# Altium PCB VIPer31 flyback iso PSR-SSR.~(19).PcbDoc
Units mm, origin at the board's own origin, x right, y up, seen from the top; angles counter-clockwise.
Board outline 152.4 x 101.6 mm, 2 copper layers (Top Layer, Bottom Layer); 61 components, 31 nets, 135 pads, 7 vias.
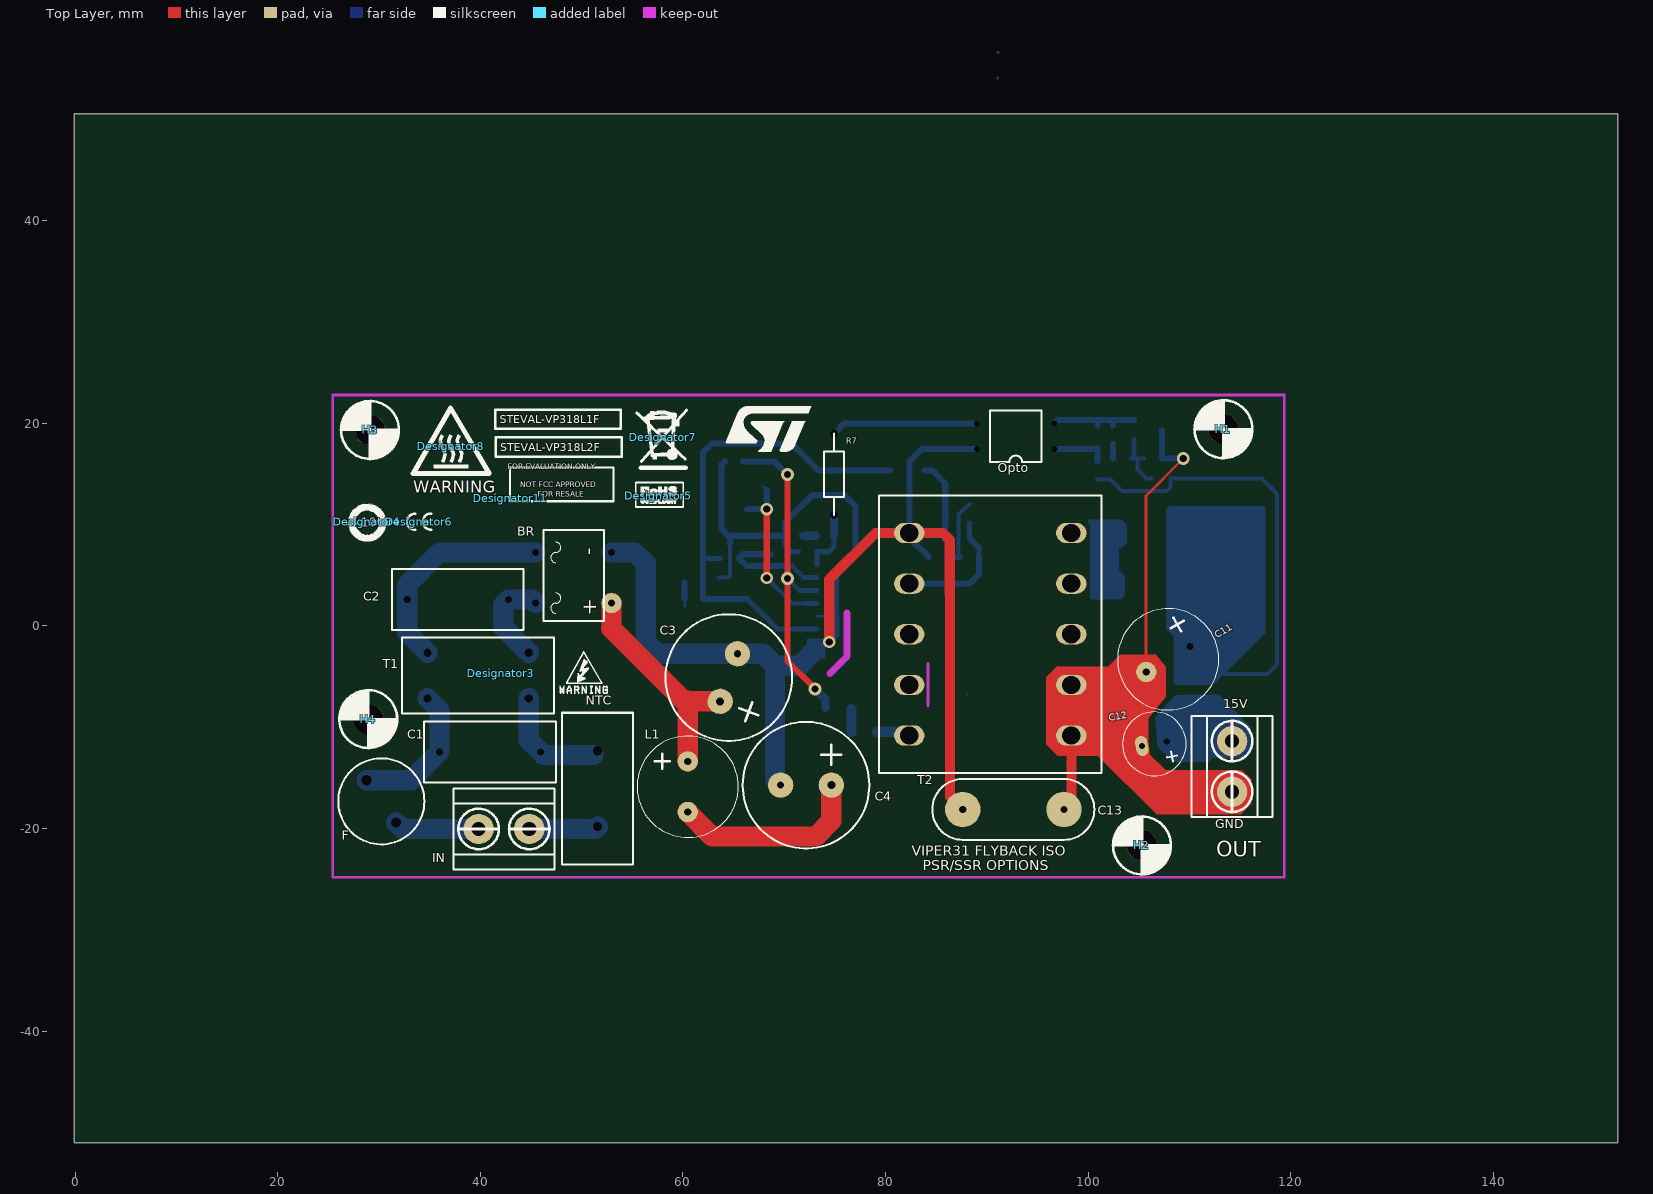
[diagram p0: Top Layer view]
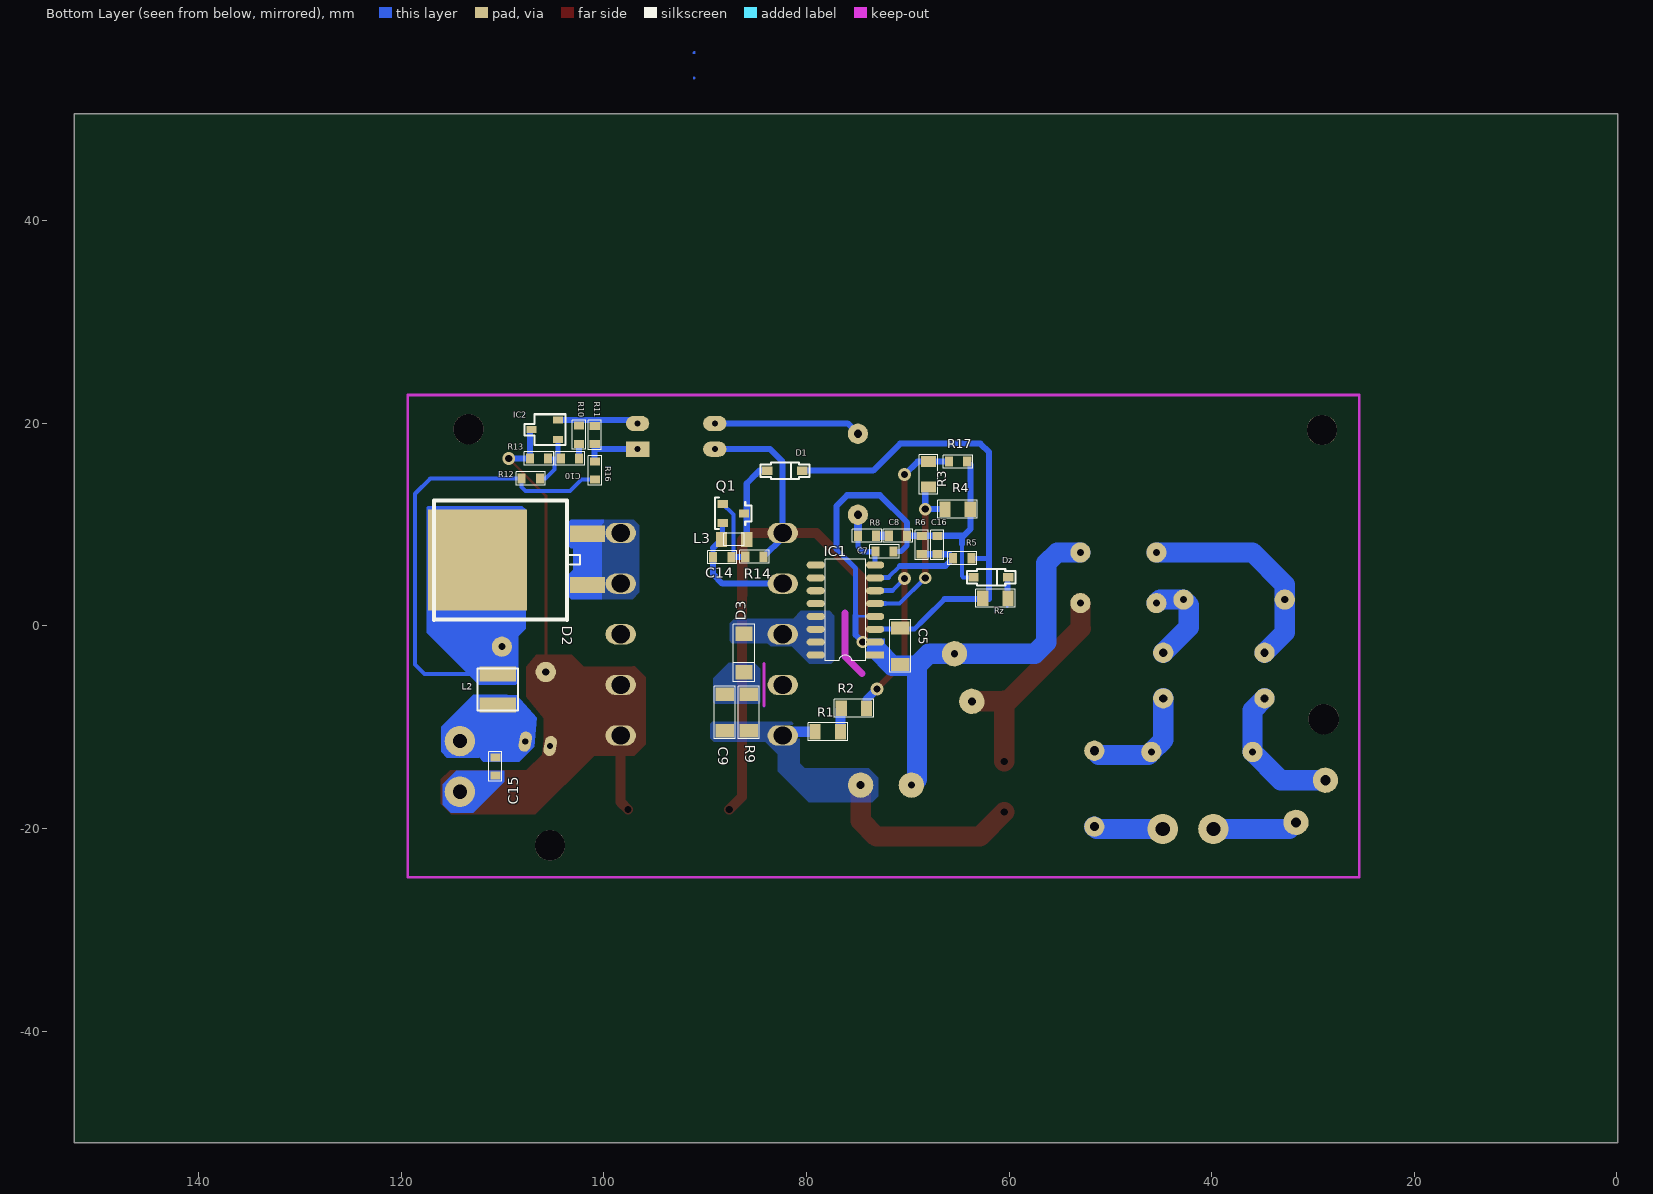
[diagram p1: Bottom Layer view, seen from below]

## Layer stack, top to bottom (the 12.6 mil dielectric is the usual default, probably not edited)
Top Solder: solder mask 0.0102, Solder Resist, Dk 3.5
Top Layer: signal copper 0.0356
Dielectric 1: dielectric 0.32, FR-4, Dk 4.8
Bottom Layer: signal copper 0.0356
Bottom Solder: solder mask 0.0102, Solder Resist, Dk 3.5

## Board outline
-0.1,-51.05 152.3,-51.05 152.3,50.55 -0.1,50.55

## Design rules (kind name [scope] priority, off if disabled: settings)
Clearance Clearance_1 [All] p1: gap=0.2 ignorepadtopadclearanceinfootprint=FALSE except(0: Arc-Hole Track-Hole SMDPad-Hole THPad-Hole Via-Hole Fill-Hole Poly-Hole Region-Hole Text-Hole)
Clearance [All] p2: gap=0.254 ignorepadtopadclearanceinfootprint=FALSE except(0: Arc-Poly Arc-Hole Track-Poly Track-Region Track-Hole SMDPad-Poly SMDPad-Hole THPad-Poly THPad-Hole Via-Poly Via-Hole Fill-Poly Fill-Hole Poly-Poly Poly-Hole Region-Hole Text-Hole)
PolygonConnect [All] p1: connectstyle=Direct reliefconductorwidth=0.254 reliefentries=4 polygonreliefangle="90 Angle" airgapwidth=0.254
RoutingVias [All] p1: holewidth=0.711 width=1.27 viastyle="Through Hole" minholewidth=0.711 minwidth=1.27 maxholewidth=0.711 maxwidth=1.27
SolderMaskExpansion [All] p1: expansion=0.102
Width [All] p1: maxlimit=2 minlimit=0.254 preferedwidth=0.254 minimp=50.000000 maximp=50.000000 favimp=50.000000
30 further rules are at their usual default settings.

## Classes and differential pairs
component class "VIPer31 flyback iso PSR-SSR": BR C1 C2 C4 C5 C7 C8 C9 C10 C13 C14 C16 D1 D2 D3 Dz F H1 H2 H3 H4 IC1 IC2 IN L1 L3 NTC Opto Q1 R1 R2 R3 R4 R5 R6 R7 R8 R9 R10 R11 R12 R13 R14 R16 R17 Rz T1 T2 VR1

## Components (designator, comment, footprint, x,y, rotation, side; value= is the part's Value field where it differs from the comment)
BR "MB6S-E3" BRIDGE 45.45,7.25 r270 top
C1 "100nF" CAP-13X6 45.95,-12.45 r180 top value="100 pF +/-5%, 250 Vdc"
C2 "100nF" CAP-13X6 42.775,2.6 r180 top value="100 pF +/-5%, 250 Vdc"
C3 "22 uF 400 Vcc" CAPOL-5X12.5 63.675,-7.45 r70 top value="68 uF +/-20%, 400 Vcc, +105°C"
C4 "22 uF 400 Vcc" CAPOL-5X12.5 74.65,-15.725 r180 top value="68 uF +/-20%, 400 Vcc, +105°C"
C5 "4.7uF" R-1206-B2 70.75,-0.2 r270 top value="10uF +/-20%, 35 Vcc, +105°C"
C7 "1 nF 200 Vdc" R-0603-B2 73.2,7.35 r180 top value="1 nF +/-5%, 200 Vdc"
C8 "NC" R-0603-B2 71.875,8.9 r180 top
C9 "1nF +/-5% 630V" R-1206-B2 88.075,-10.35 r90 top value="1 nF 630 Vdc"
C10 "47nF" R-0603-B2 104.265,16.525 r180 top value="22nF, ±10%, 100Vcc"
C11 "680 uF, 25 Vcc" CAPOL-5X10#1 110.075,-2.05 r210 top value="470 uF +/-20%, 35 Vcc, +105°C"
C12 "100 uF, 35 Vcc" CAPOL-2.5X6.3 107.775,-11.425 r10 top value="100 uF +/-20%, 35 Vcc, +105°C"
C13 "2.2nF 250Vac X1 Y2" MYLAR-10X6 97.625,-18.125 r180 top value="2.2 nF 250 Vac X1 Y2"
C14 "NC" R-0603-B2 87.425,6.775 r0 top
C15 "100 nF" R-0603-B2 110.725,-12.975 r270 top value="100nF ±10%, 25 Vcc"
C16 "NC" R-0603-B2 67.075,7.075 r90 top
D1 "1N4148" SOD-123 83.875,15.325 r0 top value="1 A, 150 V"
D2 "STPS20200CG-TR" D2PAK 101.625,4.025 r90 bottom
D3 "MRA4007T3G" SMA-2 86.175,-0.775 r90 top
Designator3 "Comment" High-Voltage-Logo-5mm 42,-4.675 r0 top
Designator4 "Comment" "RoHS-CH-Logo 10-4mm" 28.775,10.275 r0 top
Designator5 "Comment" RoHS-EU-Logo-4.5mm 57.55,12.85 r0 top
Designator6 "Comment" "CE 1.85 x 2.76mm" 33.9,10.275 r0 top
Designator7 "Comment" WASTE_5mm 58,18.65 r0 top
Designator8 "Comment" "HOT SURFACE-logo-8mm" 37.05,17.725 r0 top
Designator11 "Comment" ADVISE_small 42.95,12.6 r0 top
Dz "22" SOD-123 63.525,4.8 r0 top value="18W, 500 mW"
F "2A" Fuse_3821200041_Wick 31.675,-19.4 r125 top
H1 "HOLE" FORO 113.375,19.425 r0 top
H2 "HOLE" FORO 105.325,-21.675 r0 top
H3 "HOLE" FORO 29.1,19.35 r0 top
H4 "HOLE" FORO 28.925,-9.2 r0 top
IC1 "VIPER31_SO16" SO-16N_2 73.225,-2.875 r90 top
IC2 "TS3431BILT" SOT23-3-MIRR 104.54,20.325 r270 top value="1.24 V VREF SHUNT"
IN "input connector" SM.2VITE 39.825,-20.05 r0 top
L1 "1mH" CAPOL-5X10#2 60.475,-13.375 r270 top value="3.3UH 3.23A 33 MOHM"
L2 "3.3 uH" WE_74404043033A_4x4 110.5,-4.75 r90 top value="3.3UH 3.23A 33 MOHM"
L3 "10uH" R-0805-B 85.9,8.525 r0 top value="3.3UH 3.23A 33 MOHM"
NTC "10 Ohm" B57237S100M-NTC 51.575,-19.825 r90 top
Opto "SFH610A-2" DIP4 96.675,17.45 r180 top
OUT "output connector" SM.2VITE 114.225,-11.375 r270 top
Q1 "BC807" BC817_NEW 88.275,10.3 r90 top value="PNP Transitstor 0.5A, 45 V, hfe 30"
R1 "3 MOhm" R-0805-B2 76.65,-10.45 r0 top value="1MOhm +/-5%"
R2 "3 MOhm" R-0805-B2 74.075,-8.125 r0 top value="1MOhm +/-5%"
R3 "6.8 kOhm" R-0805-B2 67.95,13.725 r90 top value="1MOhm +/-5%"
R4 "60.4 kOhm" R-0805-B2 63.825,11.525 r0 top value="1MOhm +/-5%"
R5 "NC" R-0603-B2 65.525,6.675 r180 top
R6 "0R" R-0603-B2 68.625,8.875 r270 top value="0 Ohm, 0.25W"
R7 "0R" RES-1/4W-3 74.925,18.975 r270 top value="0 Ohm, 0.25W"
R8 "NC" R-0603-B2 73.125,8.9 r0 top
R9 "220 kOhm" R-1206-B2 85.7,-6.75 r270 top value="220 KOhm +/-5%, 0.33W, 1206"
R10 "82k" R-0603-B2 102.465,17.975 r90 top value="470kO ±1%, 0.1W"
R11 "15k" R-0603-B2 100.915,19.75 r270 top value="22KO ±1%, 0.1W"
R12 "100 kOhm" R-0603-B2 106.325,14.55 r0 top value="130 kO ±1%, 0.1 W"
R13 "9 kOhm" R-0603-B2 107.315,16.525 r180 top value="15 kO ±1%, 0.1W, 0603"
R14 "NC" R-0603-B2 84.25,6.825 r0 top
R16 "2.2k" R-0603-B2 100.89,16.25 r270 top value="470O ±1%, 0.1W"
R17 "RESISTENZA" R-0603-B2 64.125,16.225 r0 top
Rz "12R" R-0805-B2 60.1,2.725 r0 top value="47O ±1%, 0.125W"
T1 "2 X 10 mH" WE_744821110_Choke 44.775,-2.65 r90 top
T2 "TRANSFORMER_WURTH_750317580-VIPer31" WURTH-750317580-VIPer31 82.35,9.175 r0 top

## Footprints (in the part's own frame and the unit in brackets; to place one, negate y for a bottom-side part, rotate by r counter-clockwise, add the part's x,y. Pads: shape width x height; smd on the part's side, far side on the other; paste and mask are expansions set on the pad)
ADVISE_small [mm]
  silkscreen extent -0.04,-0.29 10.2,3.02
B57237S100M-NTC [mm]
  round 0 / inner round 0 / far side round 2 hole 0.9: 1(0,0) 2(7.5,0)
  silkscreen extent -3.75,-3.5 11.25,3.5
BC817_NEW [mm]
  rect 0.8x1 smd far side: 1(1.75,0) 2(-0.15,0) 3(0.8,2.1)
BRIDGE [mm]
  round 0 / inner round 0 / far side round 2 hole 0.7: 1(0,0) 3(5,0) 4(0,7.5)
  round 2 hole 0.7: 2(5,7.5)
  silkscreen extent -2.22,0.78 6.77,6.78
CAP-13X6 [mm]
  round 0 / inner round 0 / far side round 2 hole 0.7: 1(0,0) 2(10,0)
  silkscreen extent -1.5,-3 11.5,3
CAPOL-2.5X6.3 [mm]
  round 0 / inner round 0 / far side oval 1.2x2 hole 0.6: 1(0,0)
  oval 1.2x2 hole 0.6: 2(-2.5,0)
  silkscreen extent -4.4,-3.15 1.9,3.15
CAPOL-5X10#1 [mm]
  round 0 / inner round 0 / far side round 2 hole 0.7 unplated: 1(0,0)
  round 2 hole 0.7: 2(5,0)
  silkscreen extent -2.5,-5 7.5,5
CAPOL-5X10#2 [mm]
  round 2 / inner round 0 / far side round 0 hole 0.7: 1(0,0) 2(5,0)
  silkscreen extent -2.5,-5 7.5,5
CAPOL-5X12.5 [mm]
  round 2.5 hole 0.8: 1(0,0)
  round 2.5 hole 0.7: 2(5,0)
  silkscreen extent -3.75,-6.25 8.75,6.25
"CE 1.85 x 2.76mm" [mm]
  silkscreen extent -1.15,-0.8 1.25,0.82
D2PAK [mm]
  rect 1.6x3.5 smd: 1(0,0) 2(5.08,0)
  rect 10x9.75 smd: 3(2.475,10.85)
  silkscreen extent -3.42,0.72 8.35,15.15
DIP4 [mm]
  rect 0x0 / inner rect 0x0 / far side rect 2.3x1.5 hole 0.6 unplated: 1(0,0)
  round 0 / inner round 0 / far side oval 2.3x1.5 hole 0.6 unplated: 2(0,-2.54) 3(7.62,-2.54) 4(7.62,0)
  silkscreen extent 1.27,-3.81 6.35,1.27
FORO [mm]
  round 3 hole 3: 1(0,0)
  silkscreen extent -2.88,-2.88 2.86,2.86
Fuse_3821200041_Wick [mm]
  round 0 / inner round 0 / far side round 2.5 hole 1: 1(0,0) 2(5.08,0)
  silkscreen extent -1.71,-4.25 6.79,4.25
High-Voltage-Logo-5mm [mm]
  silkscreen extent 5.83,-1.99 10.55,2.13
"HOT SURFACE-logo-8mm" [mm]
  silkscreen extent -3.68,-2.67 3.81,3.81
MYLAR-10X6 [mm]
  round 3.5 / inner round 0 / far side round 0 hole 0.7: 1(0,0) 2(10,0)
  silkscreen extent -3,-3 13,3
R-0603-B2 [mm]
  rect 0.8x1 smd far side: 1(0,0) 2(1.8,0)
R-0805-B [mm]
  rect 1.1x1.5 smd far side: 1(0,0) 2(2.5,0)
R-0805-B2 [mm]
  rect 1.1x1.5 smd far side: 1(0,0) 2(2.5,0)
R-1206-B2 [mm]
  rect 1.3x1.8 smd far side: 1(0,0) 2(3.6,0)
RES-1/4W-3 [mm]
  round 0 / inner round 0 / far side round 2 hole 0.8: 1(0,0) 2(8,0)
  silkscreen extent 0,-1 8,1
"RoHS-CH-Logo 10-4mm" [mm]
  silkscreen extent -2.05,-1.88 2.14,1.74
RoHS-EU-Logo-4.5mm [mm]
  silkscreen extent -2.21,-1.11 2.5,1.31
SM.2VITE [mm]
  round 3 hole 1.4: 1(0,0) 2(5,0)
  silkscreen extent -2.5,-4 7.5,4
SMA-2 [mm]
  rect 1.45x1.65 smd far side: 1(0,0) 2(-3.8,0)
SO-16N_2 [mm]
  rect 0.7x1.8 smd far side: 1(0,0)
  oval 0.7x1.8 smd far side: 2(1.27,0) 3(2.54,0) 4(3.81,0) 5(5.08,0) 6(6.35,0) 7(7.62,0) 8(8.89,0) 9(8.89,-5.864) 10(7.62,-5.864) 11(6.35,-5.864) 12(5.08,-5.864) 13(3.81,-5.864) 14(2.54,-5.864) 15(1.27,-5.864) 16(0,-5.864)
SOD-123 [mm]
  rect 1x0.8 smd far side: 1(0,0) 2(-3.45,0)
SOT23-3-MIRR [mm]
  rect 0.7x1 smd far side: 1(1.9,0) 2(0.95,2.6) 3(0,0)
WASTE_5mm [mm]
  silkscreen extent -2.67,-3.03 2.46,2.77
WE_744821110_Choke [mm]
  round 0 / inner round 0 / far side round 2 hole 0.8: 1(-4.5,0) 2(0,0) 3(0,10) 4(-4.5,10)
  silkscreen extent -6,-2.5 1.5,12.5
WE_74404043033A_4x4 [mm]
  rect 1.5x3.6 smd far side: 1(0,0) 2(-3.05,0)
WURTH-750317580-VIPer31 [mm]
  oval 3x2 hole 1.8: 1(0,0) 2(0,-5) 3(0,-10) 4(0,-15) 5(0,-20) 6(16,-20) 7(16,-15) 8(16,-10) 9(16,-5) 10(16,0)
  silkscreen extent -3,-23.7 19,3.7

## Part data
BR: library part BRIDGE1, "Diode Bridge"
C1 C2: library part CAP, "100 pF 250 Vdc multi layer capacitor", Package="SMD 0603", Part number=CGA3E3C0G2E101J080AA
C3 C4: library part "Cap Pol1", "Polarized Capacitor (Radial)", Package="TH D{}18 mm, H{}25 mm, P{}7.5 mm", Part number=400BXC68MEFC18X25
C5: library part "Cap Pol1", "Vcc cap 4.7uF 50 Vcc, Kemet", Package="TH D{}4 mm, H{}7 mm, P{}1.5 mm", Part number=35ML10MEFC4X7
C7: library part CAP, "1 nF 200 Vdc multi layer capacitor", Package="SMD 0603", Part number=C0603C102J2GACAUTO
C8 C14 C16: library part CAP, Package="SMD 0603"
C9: library part CAP, "1 nF 630 V multi layer capacitor", Package="SMD 1206", Part number=C3216C0G2J102J085AA
C10: library part CAP, "22 nF +/-10%, 100 Vcc, MLCC", Package="SMD 0603", Part number=GCM188R72A223KA37D
C11: library part "Cap Pol1", "470 uF +/-20%, 35 Vcc, +105°C", Package="TH D{}10 mm, H{}12.5 mm, P{}5 mm", Part number=25ZLH470MEFC10X12.5
C12: library part "Cap Pol1", "100 uF +/-20%, 35 Vcc, +105°C", Package="TH D{}6.3 mm, H{}11 mm, P{}2.5 mm", Part number=35ZLH100MEFC6.3X11
C13: library part CAP, "2.2 nF 2000 V single layer capacitor", Package="TH 8 mm X 5 mm, P 7.5 mm", Part number=DE2E3KY222MA2BM01F
C15: library part CAP, "100nF ±10%, 25 Vcc, MLCC", Package="SMD 0603", Part number=C0603C104K3RACTU
D1: library part Diode, "small signal diode", Part number=STPS1150A
D2: library part DIODO-DUAL-2
D3: library part Diode, "Silicon Diode, 1 A, 1000 V"
Dz: library part "D Zener", "Zener Diode", Package="SOD 123", Part number=MMSZ5248B-V-GS08
F: library part "Fuse 1", "Fuse 2A,  250 Vca", Package="SMD 10.1mm X 1.43 mm", Part number=3403.0169.24
IC1: "Integrato"
IC2: library part TS432, "1.24 V VREF SHUNT", Package=SOT23-3, Part number=TS432ILT
IN OUT: library part M.2VITE, "Morsetti"
L1 L2 L3: library part Inductor, "FIXED IND 3.3UH 3.23A 33 MOHM", Package="Lu x La: 0,157 x 0,157\" (4,00 x 4,00 mm)", Part number=74404043033A
NTC: library part Res2, Package="TH 9 mm X 4 mm , P 5mm", Part number=NTPA7100LBMB0
Opto: library part OPTO_1, "Opto ingresso 60 Vdc", Package="TH, DIP4"
Q1: library part PNP_BC807, "PNP Transitstor 0.5A, 45 V, hfe 30", Package=SOT23-3L, Part number=BC807-40LT3G
R1 R2: library part Res1, "3 MOhm +/-1%  0.125W, 0805 Vishay", Package="SMD 1206", Part number=ERJP08J105V
R3: library part Res1, "6.8 kOhm +/-1% 0.125W, 0805 Panasonic", Package="SMD 1206", Part number=ERJP08J105V
R4: library part Res1, "60.4 kOhm +/-1% 0.125W, 0805 Panasonic", Package="SMD 1206", Part number=ERJP08J105V
R5 R8 R14: library part Res1, "Not connected", Package="SMD 0603"
R6 R7: library part Res1, "0O, 0.25W, pkg 0603, serie CRCW", Package="SMD 0603", Part number=CRCW06030000Z0EAHP
R9: library part Res1, "220 KOhm +/-5%, 0.33W, 1206, serie ERJT08", Package="SMD 1206", Part number=ERJT08J224V
R10: library part Res1, "470kO ±1%, 0.1W", Package="SMD 0603", Part number=CRCW0603470KFKEA
R11: library part Res1, "22KO ±1%, 0.1W", Package="SMD 0603", Part number=CRCW060322K0FKEA
R12: library part Res1, "Not connected", Package="SMD 0603", Part number=CRCW0603130KFKEA
R13: library part Res1, "15 kO ±1%, 0.1W, 0603", Package="SMD 0603", Part number=CRG0603F15K
R16: library part Res1, "470O ±1%, 0.1W", Package="SMD 0603", Part number=CRCW0603470RFKEA
R17: "Resistor"
Rz: library part Res1, "47O ±1%, 0.125W", Package="SMD 0805", Part number=CRG0805F47R
T1: library part "CM CHOKE", "Common Mode Choke, Lo=10 mH, Rdc=350 mOhm, Idc=0.7A, Un=230 Vac", Package="TH D 15 mm X 7.5 mm", Part number=744821110
T2: "Center-tapped transformer"

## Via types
v1: diameter 1.27, hole 0.711, Top Layer to Bottom Layer, 4 vias
v2: diameter 1.2, hole 0.7, Top Layer to Bottom Layer, 3 vias

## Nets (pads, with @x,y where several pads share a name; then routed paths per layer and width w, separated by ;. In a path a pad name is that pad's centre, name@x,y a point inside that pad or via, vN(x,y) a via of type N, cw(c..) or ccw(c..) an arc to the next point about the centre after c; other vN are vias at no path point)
15V: C12.1 C15.1 L2.2 OUT.1
GND: BR.4 C3.2 C4.2 C5.2 C7.2 C8.2 C13.2 C16.2 Dz.1 IC1.1 IC1.2 IC1.4 Opto.4 R4.1 R6.1 R14.1 R17.1 T2.1 | length 155.7
  Top Layer w0.254: 86.375,-16.875 86.375,-16.625
  Top Layer w1: v2(74.445,-1.605) 74.445,4.595 79.025,9.175 T2.1 85.675,9.175 86.35,8.5 86.35,3.05 ; 86.375,-16.875 C13.2 ; 86.375,-16.625 86.375,3.325
  Bottom Layer w0.254: 64.475,8.9 64.65,8.725 ; IC1.4 75.06,0.935 75.15,1.025 ; T2.1@82.35,8.725 T2.1
  Bottom Layer w0.4: Dz.1 64.525,4.8 64.65,4.925 64.65,8.1
  Bottom Layer w0.5: C8.2 70.075,7.95 70.675,7.35 C7.2 ; 75.15,1.025 75.15,5.675 77.05,7.575
  Bottom Layer w0.6: R17.1 63.825,15.925 R4.1 63.825,9.55 64.475,8.9 68.625,8.9 C8.2 70.075,10.225 72.75,12.9 75.984,12.9 77.05,11.834 77.05,7.575 ; 64.65,8.1 64.65,8.725 ; IC1.2 v2(74.445,-1.605) 75.15,-0.9 75.15,1.025 ; T2.1@82.35,8.725 R14.1 ; T2.1 82.35,16.2 83.6,17.45 Opto.4
  Bottom Layer w2: BR.4 55.25,7.25 56.325,6.175 56.325,-1.625 57.452,-2.752 C3.2 67.927,-2.752 69.1,-3.925 ; C4.2 69.1,-15.175 69.1,-3.925 ; 73.075,-2.375 71.525,-3.925 69.1,-3.925
GND2: C11.2 C12.2 C13.1 C15.2 IC2.2 OUT.2 R13.1 T2.6 T2.7 | length 34
  Top Layer w0.254: 105.725,-3.375 105.725,12.85 v1(109.4,16.525)
  Top Layer w1: C13.1 98.35,-17.4 T2.6
  Bottom Layer w0.254: IC2.2 IC2.2@107.415,19.375
  Bottom Layer w0.6: R13.1 v1(109.4,16.525) ; R13.1@107.315,16.675 IC2.2@107.315,19.275
NetBR_1: BR.1 C2.2 T1.3 | length 21.5
  Bottom Layer w2: T1.3 32.775,-0.65 C2.2 32.775,4.075 35.95,7.25 BR.1
NetBR_2: BR.2 C3.1 L1.1 | length 22.2
  Top Layer w0.254: 52.925,-0.25 52.95,-0.225 ; 60.075,-7.4 60.475,-7.4 60.525,-7.45
  Top Layer w2: 52.925,-0.25 60.075,-7.4 ; 52.95,-0.225 BR.2 ; L1.1 60.475,-7.4 ; 60.525,-7.45 C3.1
NetBR_3: BR.3 C2.1 T1.2 | length 9.3
  Bottom Layer w2: T1.2 42.25,-0.125 42.25,2.075 C2.1 45.1,2.6 BR.3
NetC1_1: C1.1 NTC.2 T1.1 | length 11.7
  Bottom Layer w0.254: NTC.2@51.15,-12.75 NTC.2
  Bottom Layer w2: T1.1 44.775,-11.275 C1.1 46.25,-12.75 NTC.2@51.15,-12.75
NetC1_2: C1.2 F.2 T1.4 | length 14.1
  Bottom Layer w2: F.2 33.161,-15.239 C1.2 35.95,-8.325 T1.4
NetC4_1: C4.1 C9.1 L1.2 R1.2 R9.2 T2.5 | length 22.7
  Top Layer w2: L1.2 62.9,-20.8 73.1,-20.8 74.65,-19.25 C4.1
  Bottom Layer w0.254: T2.5@81.975,-10.45 T2.5
  Bottom Layer w1: R1.2 T2.5@81.975,-10.45
NetC5_1: C5.1 D1.2 IC1.3 R5.2 Rz.2 | length 48.7
  Bottom Layer w0.254: 61.975,2.7 62,2.675 ; 61.975,6.6 62.05,6.675 ; 68.325,0.65 68.35,0.675 ; IC1.3@73.215,-0.325 IC1.3
  Bottom Layer w0.5: 62.05,6.675 R5.2 ; 66.362,2.662 68.35,0.675 69.35,-0.325 IC1.3@73.215,-0.325
  Bottom Layer w0.6: 61.975,2.7 61.975,5.95 61.975,6.6 61.975,17.15 62.825,18 70.75,18 73.425,15.325 D1.2 ; 62,2.675 66.362,2.675
NetC7_1: C7.1 IC1.8 R7.2 R8.2 | length 6.4
  Bottom Layer w0.254: IC1.8 IC1.8@73.272,6.062
  Bottom Layer w0.5: IC1.8@73.225,6.04 73.225,7.325 74.425,7.325 74.925,7.825 R8.2
  Bottom Layer w0.8: R8.2 R7.2
NetC8_1: C8.1 R8.1 | length 1.3
  Bottom Layer w0.8: C8.1 R8.1
NetC9_2: C9.2 D3.2 R9.1 | length 0
NetC10_1: C10.1 IC2.1 R12.1 R13.2 | length 6.2
  Bottom Layer w0.254: C10.1 C10.1@104.54,16.8
  Bottom Layer w0.4: C10.1 104.875,16.525 ; R13.2 104.875,16.525 ; R12.1 105.775,14.55 104.875,15.45 104.875,16.525
  Bottom Layer w0.5: C10.1@104.54,16.8 IC2.1
NetC10_2: C10.2 R10.1 | length 1.4
  Bottom Layer w0.6: C10.2 R10.1
NetC11_1: C11.1 D2.3 L2.1 R12.2 R16.2 | length 45.3
  Bottom Layer w0.4: R16.2 102.225,14.45 103.375,13.3 107.725,13.3 108.125,13.7 R12.2 117.15,14.55 118.65,13.05 118.65,-3.825 117.725,-4.75 L2.1
NetC14_1: C14.1 Q1.1 R14.2 | length 6.7
  Bottom Layer w0.254: C14.1@87.375,6.825 C14.1
  Bottom Layer w0.4: C14.1@87.225,7.15 87.225,11 ; 87.275,11.05 Q1.1
  Bottom Layer w0.6: R14.2 C14.1@87.375,6.825
NetC14_2: C14.2 L3.2 Q1.2 T2.2 | length 12.7
  Bottom Layer w0.254: L3.2@88.275,8.65 L3.2
  Bottom Layer w0.5: L3.2@88.275,8.65 Q1.2 ; C14.2 89.225,7.7
  Bottom Layer w0.6: T2.2 88.3,4.175 89.225,5.1 C14.2 ; L3.2 89.225,7.7
NetC16_1: C16.1 IC1.7 R5.1 R6.2 | length 11.8
  Bottom Layer w0.4: 70.775,5.925 71.93,4.77
  Bottom Layer w0.5: 71.93,4.77 IC1.7@73.225,4.77
  Bottom Layer w0.6: R6.2 C16.1 65.925,7.075 R5.1 66.275,5.925 70.775,5.925
NetD1_1: D1.1 L3.1 Q1.3 | length 8.4
  Bottom Layer w0.254: 85.875,14.1 85.9,14.075 ; Q1.3@85.9,11.075 85.925,11.1 Q1.3
  Bottom Layer w0.6: D1.1 84.65,15.325 85.013,14.963 85.875,14.1 ; L3.1 85.9,11.075 85.9,14.075
NetD2_1: D2.1 D2.2 T2.9 T2.10
NetD3_1: D3.1 IC1.13 IC1.14 IC1.15 IC1.16 T2.3
NetDz_2: Dz.2 Rz.1 | length 2.4
  Bottom Layer w0.254: 60.175,1.875 Rz.1@60.175,2.725
  Bottom Layer w0.6: 60.15,4.3 60.15,2.75 Rz.1@60.175,2.725
NetF_1: F.1 IN.1 | length 8.4
  Bottom Layer w2: F.1 32.325,-20.05 IN.1
NetIC1_5: IC1.5 R3.1 R4.2 | length 17.5
  Top Layer w0.6: v2(68.275,4.725) v2(68.275,11.525)
  Bottom Layer w0.254: R3.1 R3.1@68.275,13.4 ; v2@68.275,4.3 v2(68.275,4.725) ; IC1.5@73.22,2.2 IC1.5
  Bottom Layer w0.4: v2(68.275,4.725) 70.8,2.2 72.225,2.2
  Bottom Layer w0.5: 72.225,2.2 IC1.5@73.22,2.2
  Bottom Layer w0.6: R4.2 v2(68.275,11.525) R3.1@68.275,13.4
NetIC1_6: IC1.6 R2.1 R3.2 R17.2 | length 32.9
  Top Layer w0.6: v1(70.325,14.95) v1(70.325,4.675) 70.325,-3.5 v1(73.05,-6.225)
  Bottom Layer w0.4: v1(70.325,4.675) 71.525,3.475
  Bottom Layer w0.5: 71.525,3.475 IC1.6
  Bottom Layer w0.6: R17.2 R3.2 69.025,16.225 v1@70.3,14.95
  Bottom Layer w0.8: v1(73.05,-6.225) 74.075,-7.25 R2.1
NetIC2_3: IC2.3 Opto.2 R10.2 R11.1 | length 9.1
  Bottom Layer w0.6: Opto.2 97.01,20.325 100.915,20.325 ; R11.1 100.915,20.325 ; R10.2 102.465,20.325 ; IC2.3 102.465,20.325 ; 100.915,20.325 102.465,20.325
NetIN_2: IN.2 NTC.1 | length 6.8
  Bottom Layer w2: IN.2 51.35,-20.05 NTC.1
NetOpto_1: Opto.1 R11.2 R16.1 | length 5.6
  Bottom Layer w0.254: 100.84,17.45 100.915,17.525 ; R16.1 R16.1@100.915,16.275
  Bottom Layer w0.6: Opto.1 100.84,17.45 ; R16.1@100.915,16.275 100.915,17.525
NetOpto_3: Opto.3 R7.1 | length 14.6
  Bottom Layer w0.6: R7.1 75.94,19.99 Opto.3
NetR1_1: R1.1 R2.2 | length 2.4
  Bottom Layer w0.254: R2.2 R2.2@76.65,-8.2
  Bottom Layer w1: R1.1 R2.2@76.65,-8.2
pads on no net: H1.1 H2.1 H3.1 H4.1 IC1.9 IC1.10 IC1.11 IC1.12 T2.4 T2.8
copper on no net: | length 0.1
  Bottom Layer w0.254: 91.07,54.1 91.095,54.075 ; 91.07,56.64 91.11,56.6

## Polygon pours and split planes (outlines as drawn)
NetC4_1 on Bottom Layer "NetC4_1" (solid, pour order 64): 80.175,-14.075 80.675,-13.575 80.675,-10.25 81.475,-9.45 89.325,-9.45 89.525,-9.65 89.525,-11.1 89.175,-11.45 84.075,-11.45 82.85,-12.675 82.85,-14.35 79.8,-17.4 73.525,-17.4 72.925,-16.8 72.925,-15 73.85,-14.075
NetD2_1 on Bottom Layer "Bottom Layer-No Net 1" (solid, pour order 42): 96.475,9.5 96.5,9.475 96.5,3.3 97.15,2.65 100.225,2.65 102.725,5.15 102.725,8.025 100.25,10.5 97.05,10.5 96.5,9.95 96.5,9.475
NetD3_1 on Bottom Layer "Bottom Layer-No Net 1" (solid, pour order 46): 77.275,-3.45 77.575,-3.75 79.725,-3.75 81.45,-2.025 83.55,-2.025 83.875,-1.7 87.375,-1.7 87.6,-1.475 87.6,0.25 87.15,0.7 81.325,0.7 80.55,1.475 77.725,1.475 77.275,1.025
NetC9_2 on Bottom Layer "Bottom Layer-No Net 1" (solid, pour order 60): 84.575,-4.225 85.175,-3.625 87.675,-3.625 89.225,-5.175 89.225,-7.5 89.05,-7.675 84.7,-7.675 84.575,-7.55

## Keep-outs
Keep-Out Layer:
  lines w0.254: 25.425,-24.8 25.425,22.8 119.375,22.8 119.375,-24.8 25.425,-24.8
  lines w0.3: 84.2,-7.925 84.2,-3.725
  lines w0.7: 74.525,-4.7 76.2,-3.025 ; 76.2,-2.925 76.2,1.275

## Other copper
Top Layer:
  region net GND2: 97.2,-4.025 102,-4.025 103.2,-2.825 106.7,-2.825 107.65,-4.025 107.65,-7 105.925,-9.125 105.925,-11 105.925,-11.25 106.1,-12.7 107.65,-14.25 115.2,-14.25 116.1,-15.15 116.1,-17.575 115.075,-18.6 106.775,-18.6 100.975,-12.8 97,-12.8 95.875,-11.675 95.875,-5.075 96.95,-4 97.175,-4
Bottom Layer:
  rectangle net GND: 72.25,-3.2 74.025,-1.25
  region net GND2: 114.575,-14.325 115.9,-15.65 115.9,-17.65 115.125,-18.425 112.9,-18.425 109.85,-15.375 109.85,-14.325
  region net 15V: 109.525,-6.825 108.6,-6.825 106.625,-9.075 106.869,-11.919 108.35,-13.4 111.9,-13.4 112.325,-12.975 112.35,-13 115.525,-13 116.075,-12.45 116.075,-9.975 112.9,-6.8 109.525,-6.8
  region net NetC11_1: 107.725,-0.275 108.475,-1.025 108.475,-5.55 108.725,-5.8 112.375,-5.8 117.475,-0.7 117.475,11.725 117.375,11.825 108.05,11.825 107.725,11.5
  region net NetD2_1: 103.275,10.5 103.825,9.95 103.825,8.2 103.3,7.675 103.025,7.675 103.025,5.55 103.6,4.975 103.6,2.975 103.575,2.975 103.25,2.65 100.225,2.65 100.225,9.975 100.025,10.175 100.025,10.475 100.05,10.5

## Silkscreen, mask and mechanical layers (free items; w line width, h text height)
Top Overlay:
  drawing of 2939 lines, arcs and shapes, not listed
  text "STEVAL-VP318L1F" at 41.904,19.995 h0.8
  text "STEVAL-VP318L2F" at 41.979,17.245 h0.8
  text "15V" at 113.375,-8.45 h1.52
  text "GND" at 112.55,-20.275 h1.52
  text "VIPER31 FLYBACK ISO" at 82.6,-22.7 h1
  text "PSR/SSR OPTIONS" at 83.7,-24.15 h1
Mechanical 1:
  lines w0.254: 25.425,-28.337 25.425,-27.829 ; 26.949,-28.591 25.425,-28.083 ; 26.949,-27.575 25.425,-28.083 ; 65.138,-28.083 25.425,-28.083 ; 79.662,-28.083 119.375,-28.083 ; 117.851,-28.591 119.375,-28.083 ; 117.851,-27.575 119.375,-28.083 ; 119.375,-28.337 119.375,-27.829 ; 121.4,-23.276 121.908,-24.8 ; 121.4,21.276 121.908,22.8 ; 121.654,-24.8 122.162,-24.8 ; 121.654,22.8 122.162,22.8 ; 121.908,-7.5 121.908,-24.8 ; 121.908,5.5 121.908,22.8 ; 122.416,-23.276 121.908,-24.8 ; 122.416,21.276 121.908,22.8
  text "47.6 (mm)" at 122.822,-7.246 h1.52 r90
  text "93.95 (mm)" at 65.392,-28.997 h1.52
